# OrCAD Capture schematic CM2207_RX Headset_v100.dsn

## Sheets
1 02. Main: size A4; title: CM2207_RX Headset_Reference_Schematic; rev: 1.00; company: C-MEDIA ELECTRONICS Inc.; note: Main; note: 6F., 100, Sec. 4, Civil Boulevard, Taipei, Taiwan, R.O.C.
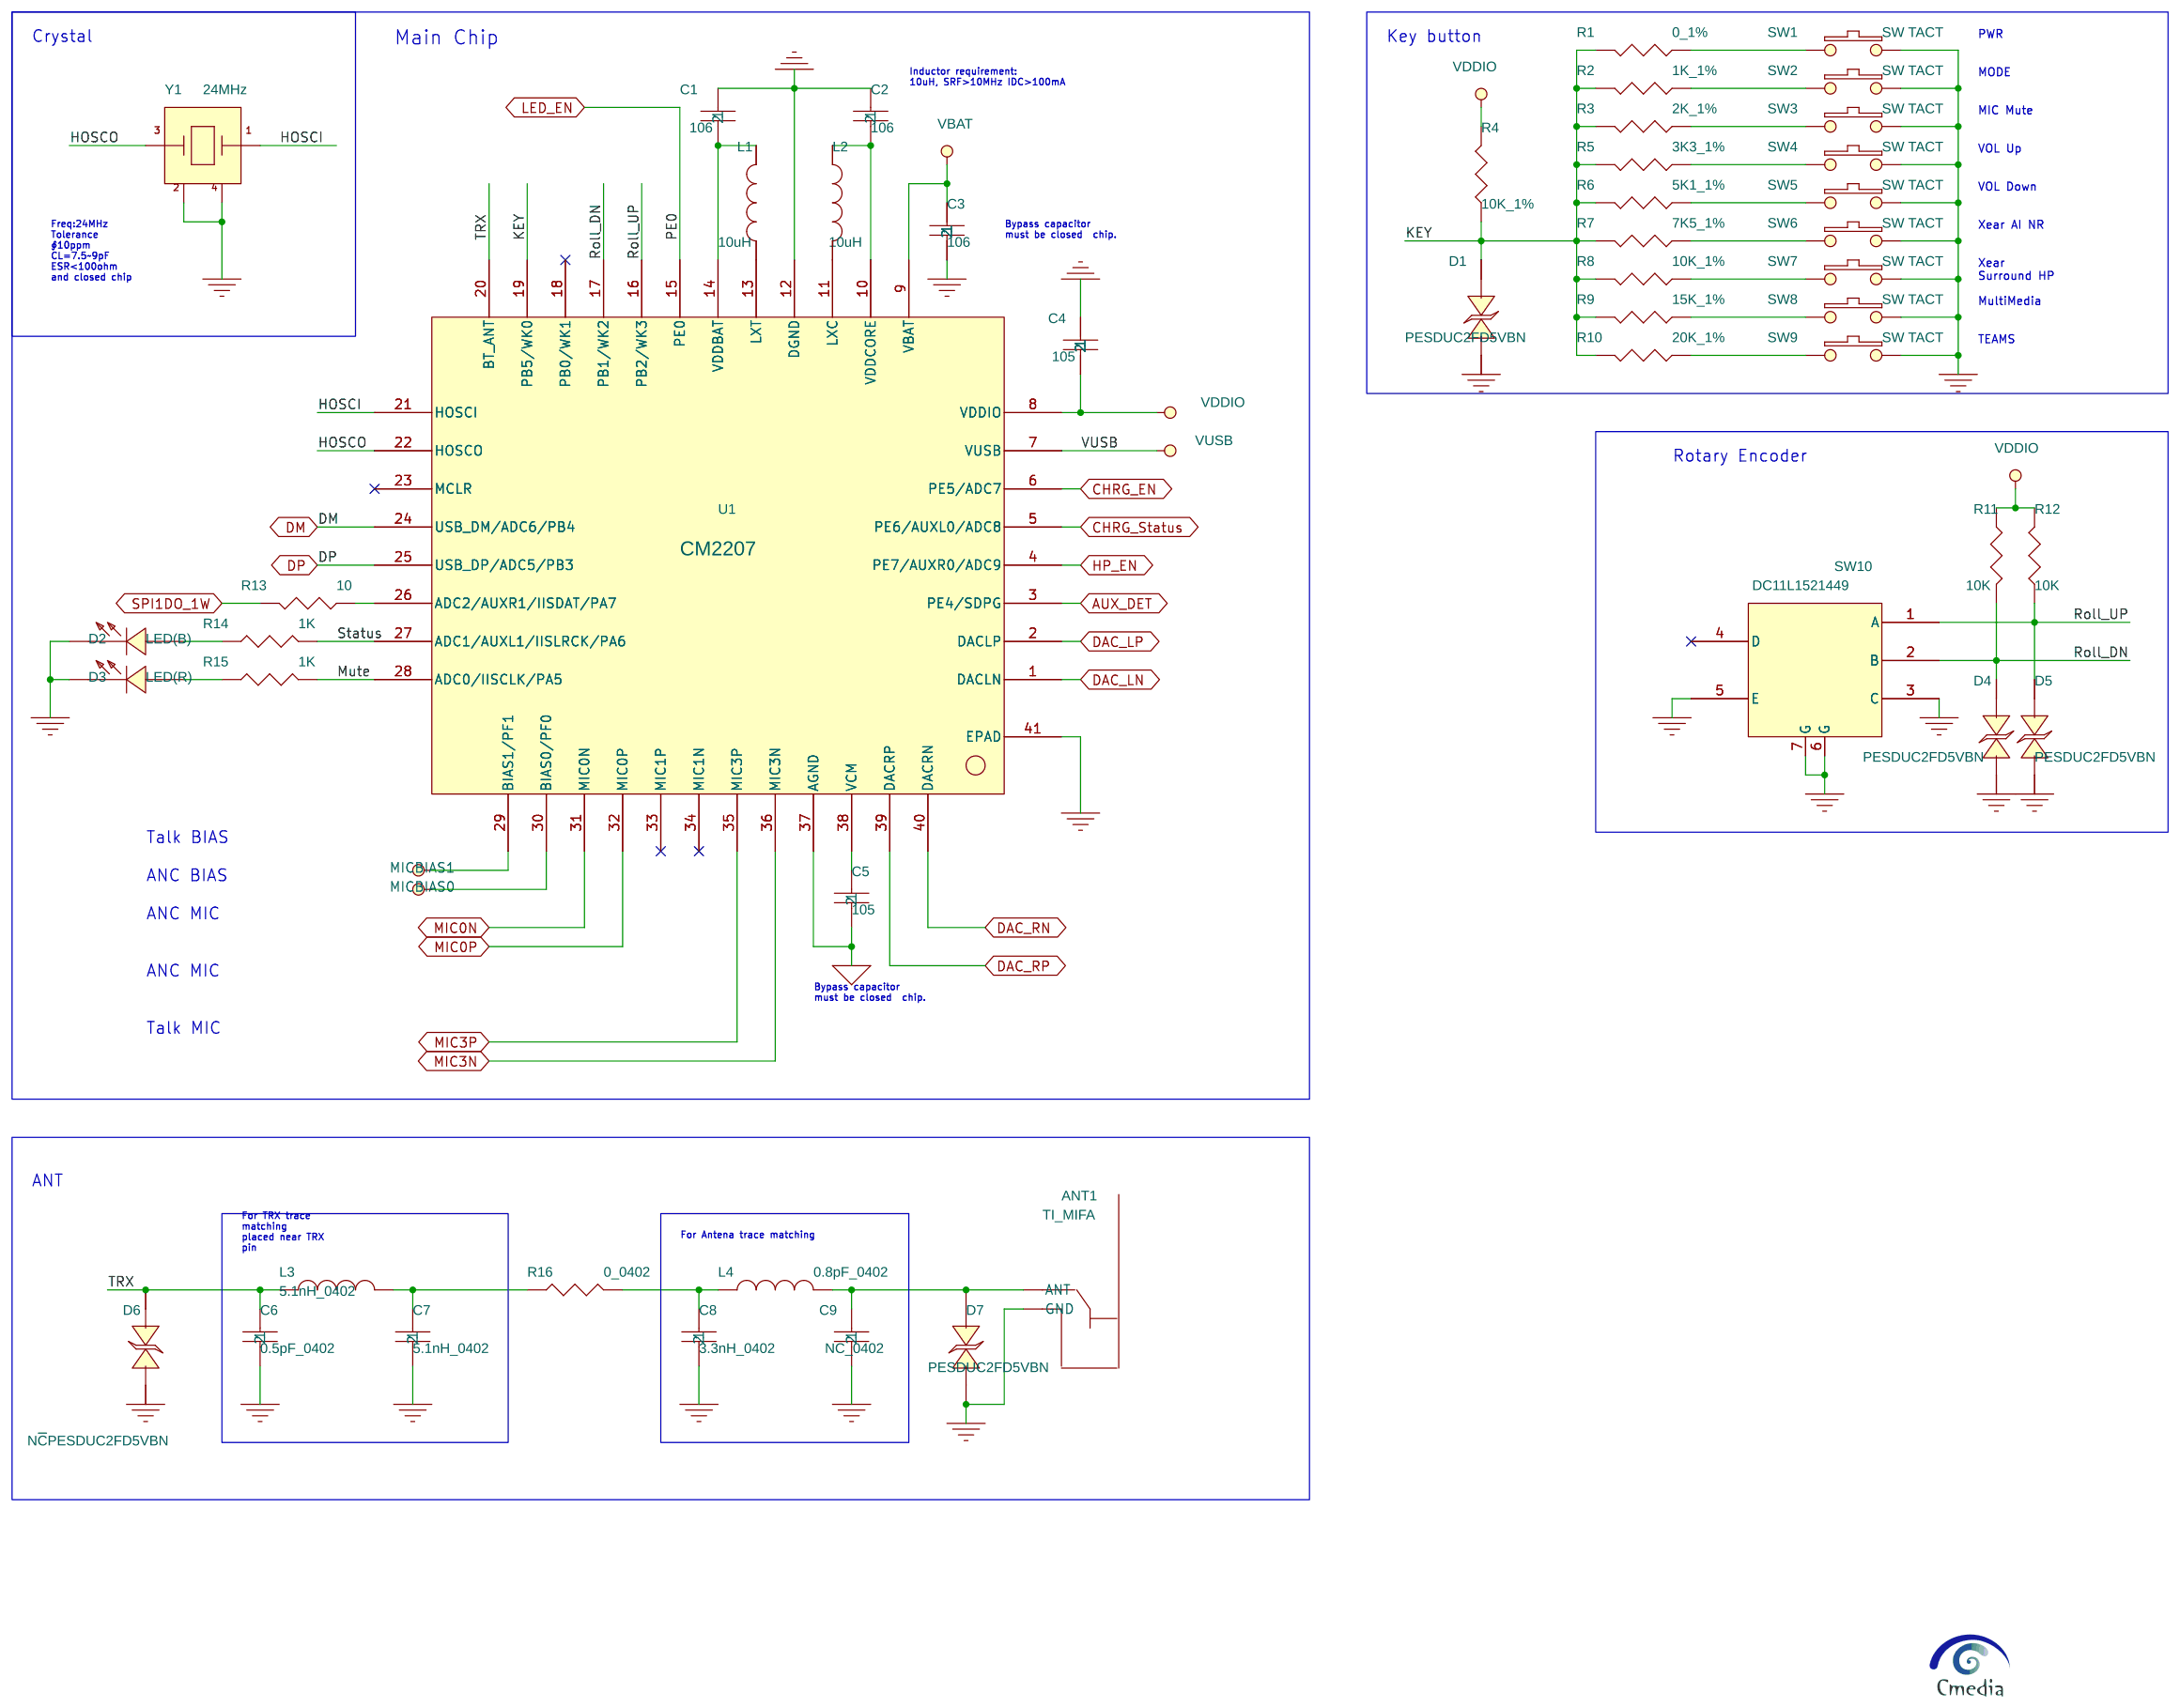
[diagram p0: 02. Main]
2 04. Headphone & Mic In & Aux In: size A4; note: Headphone & Mic In & Aux In
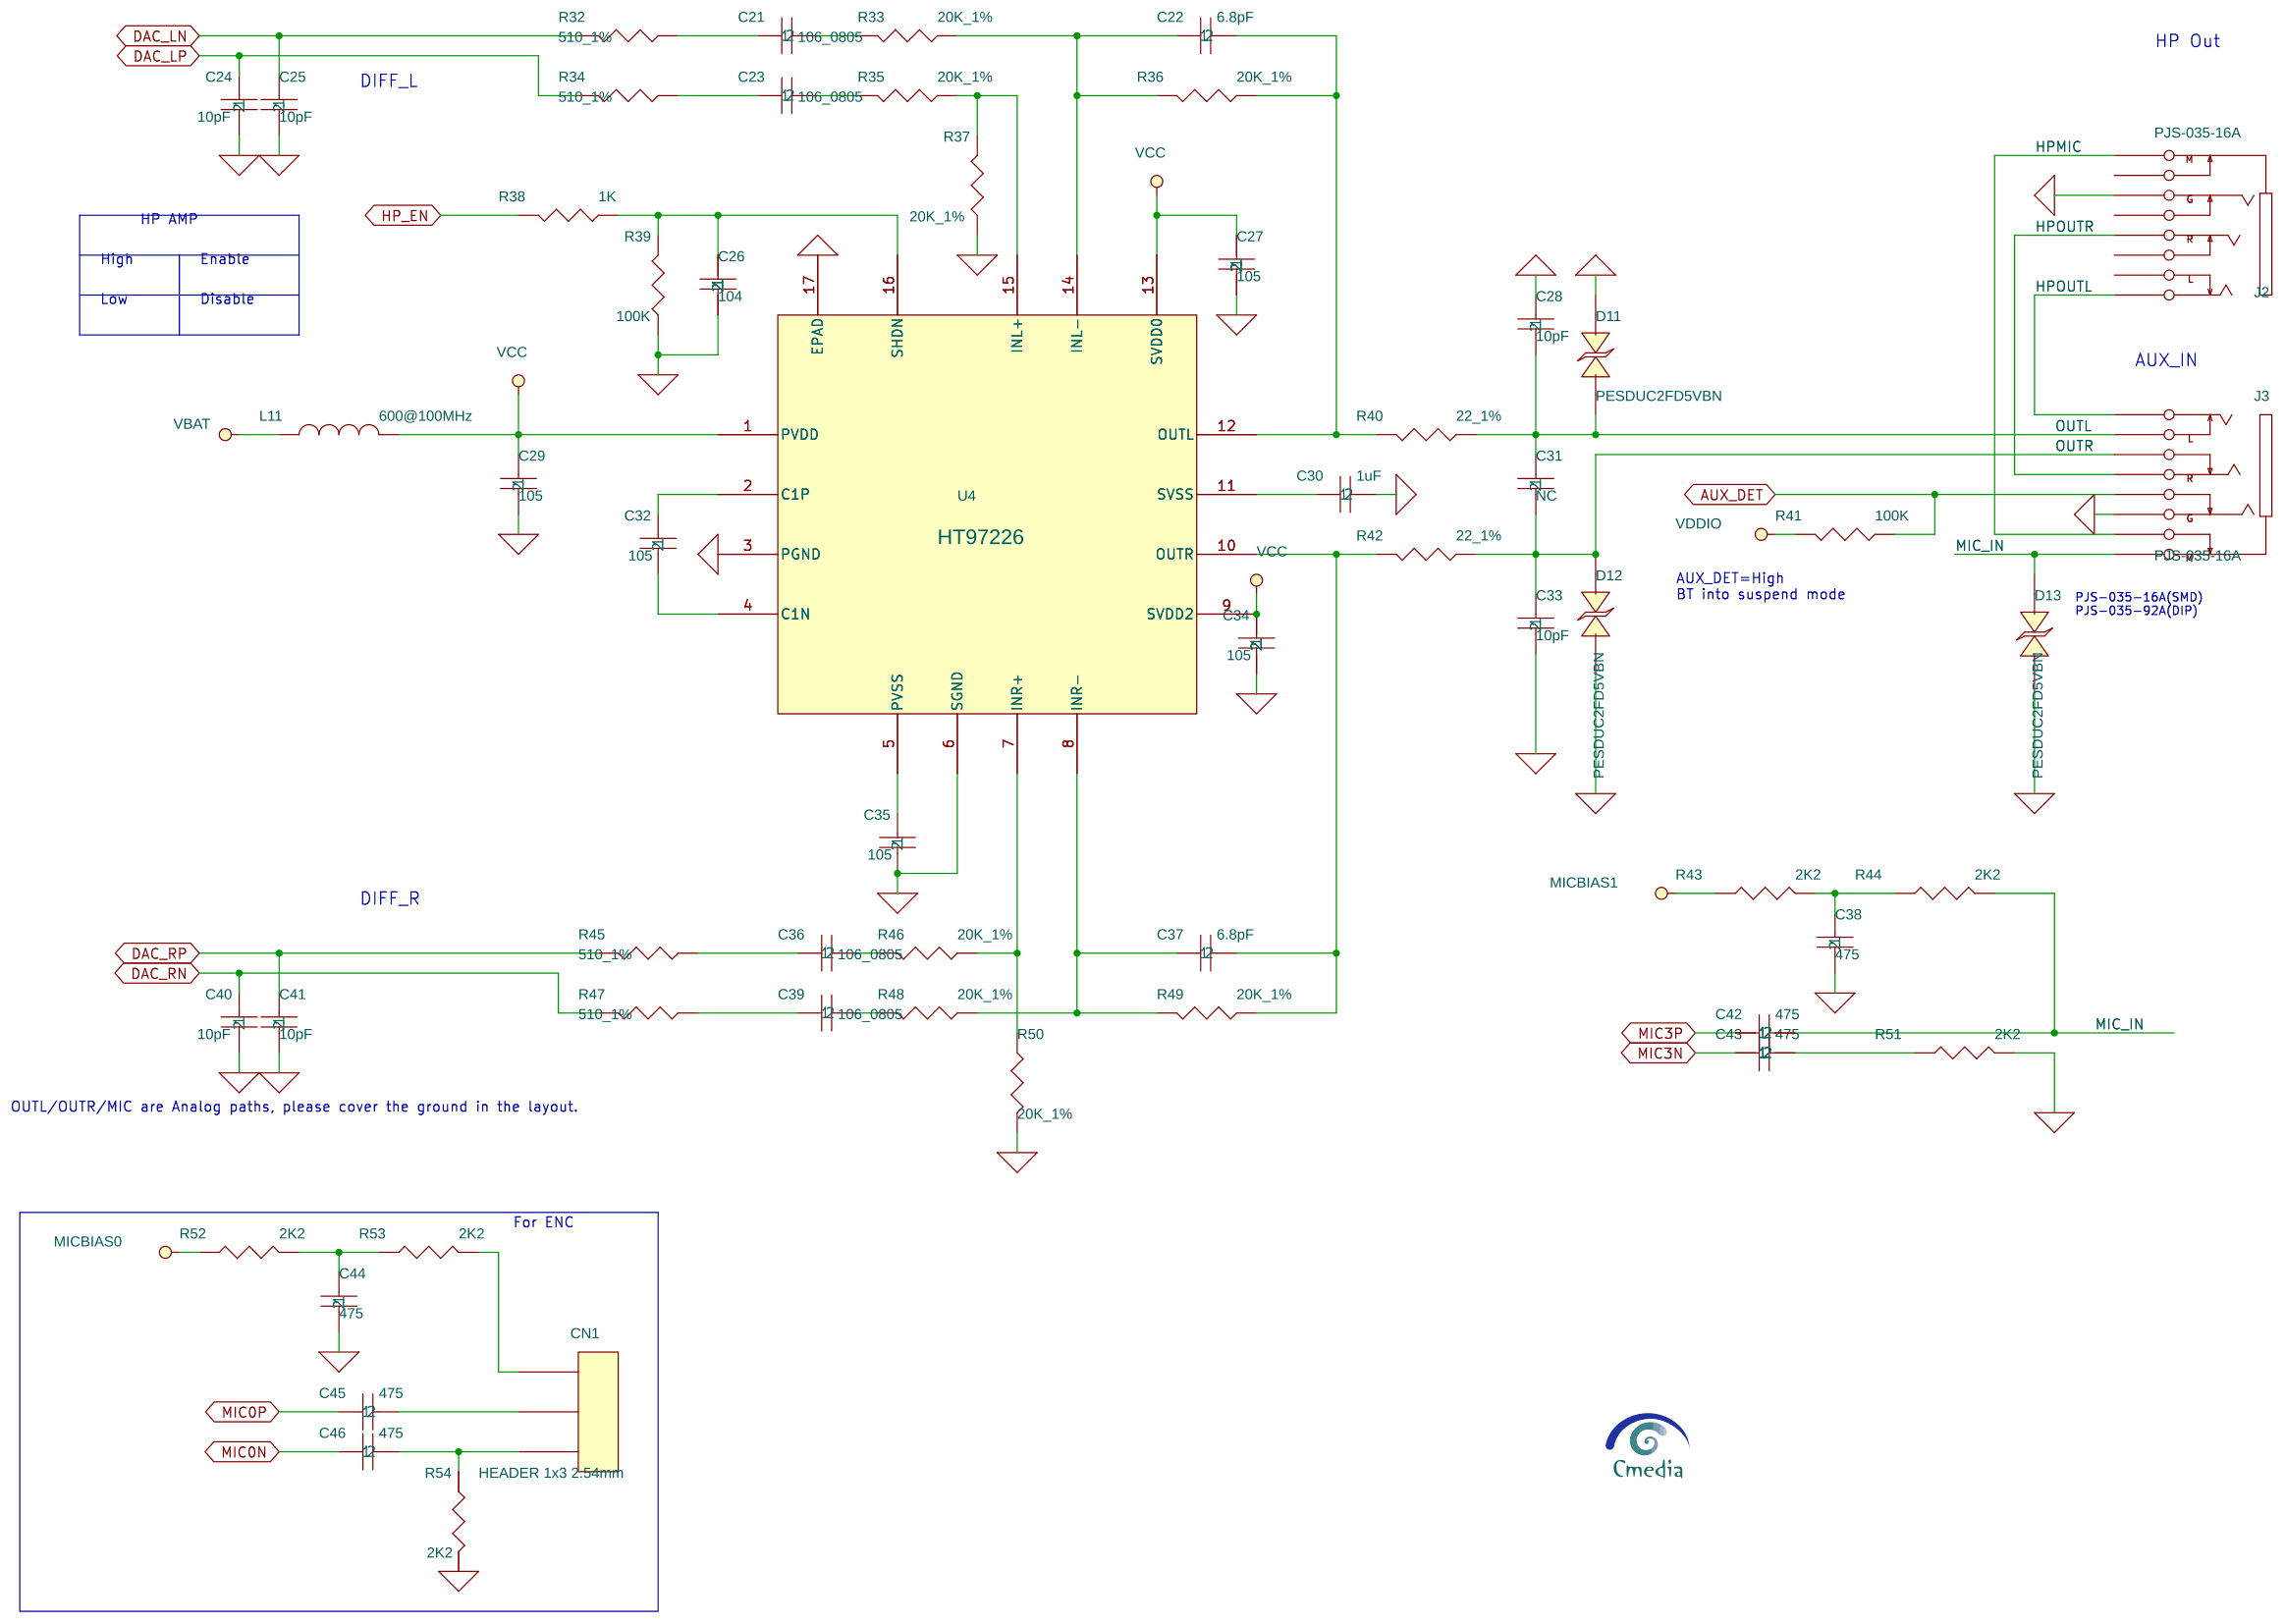
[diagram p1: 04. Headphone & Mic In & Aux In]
3 03. Power/LED: size A4; note: Power
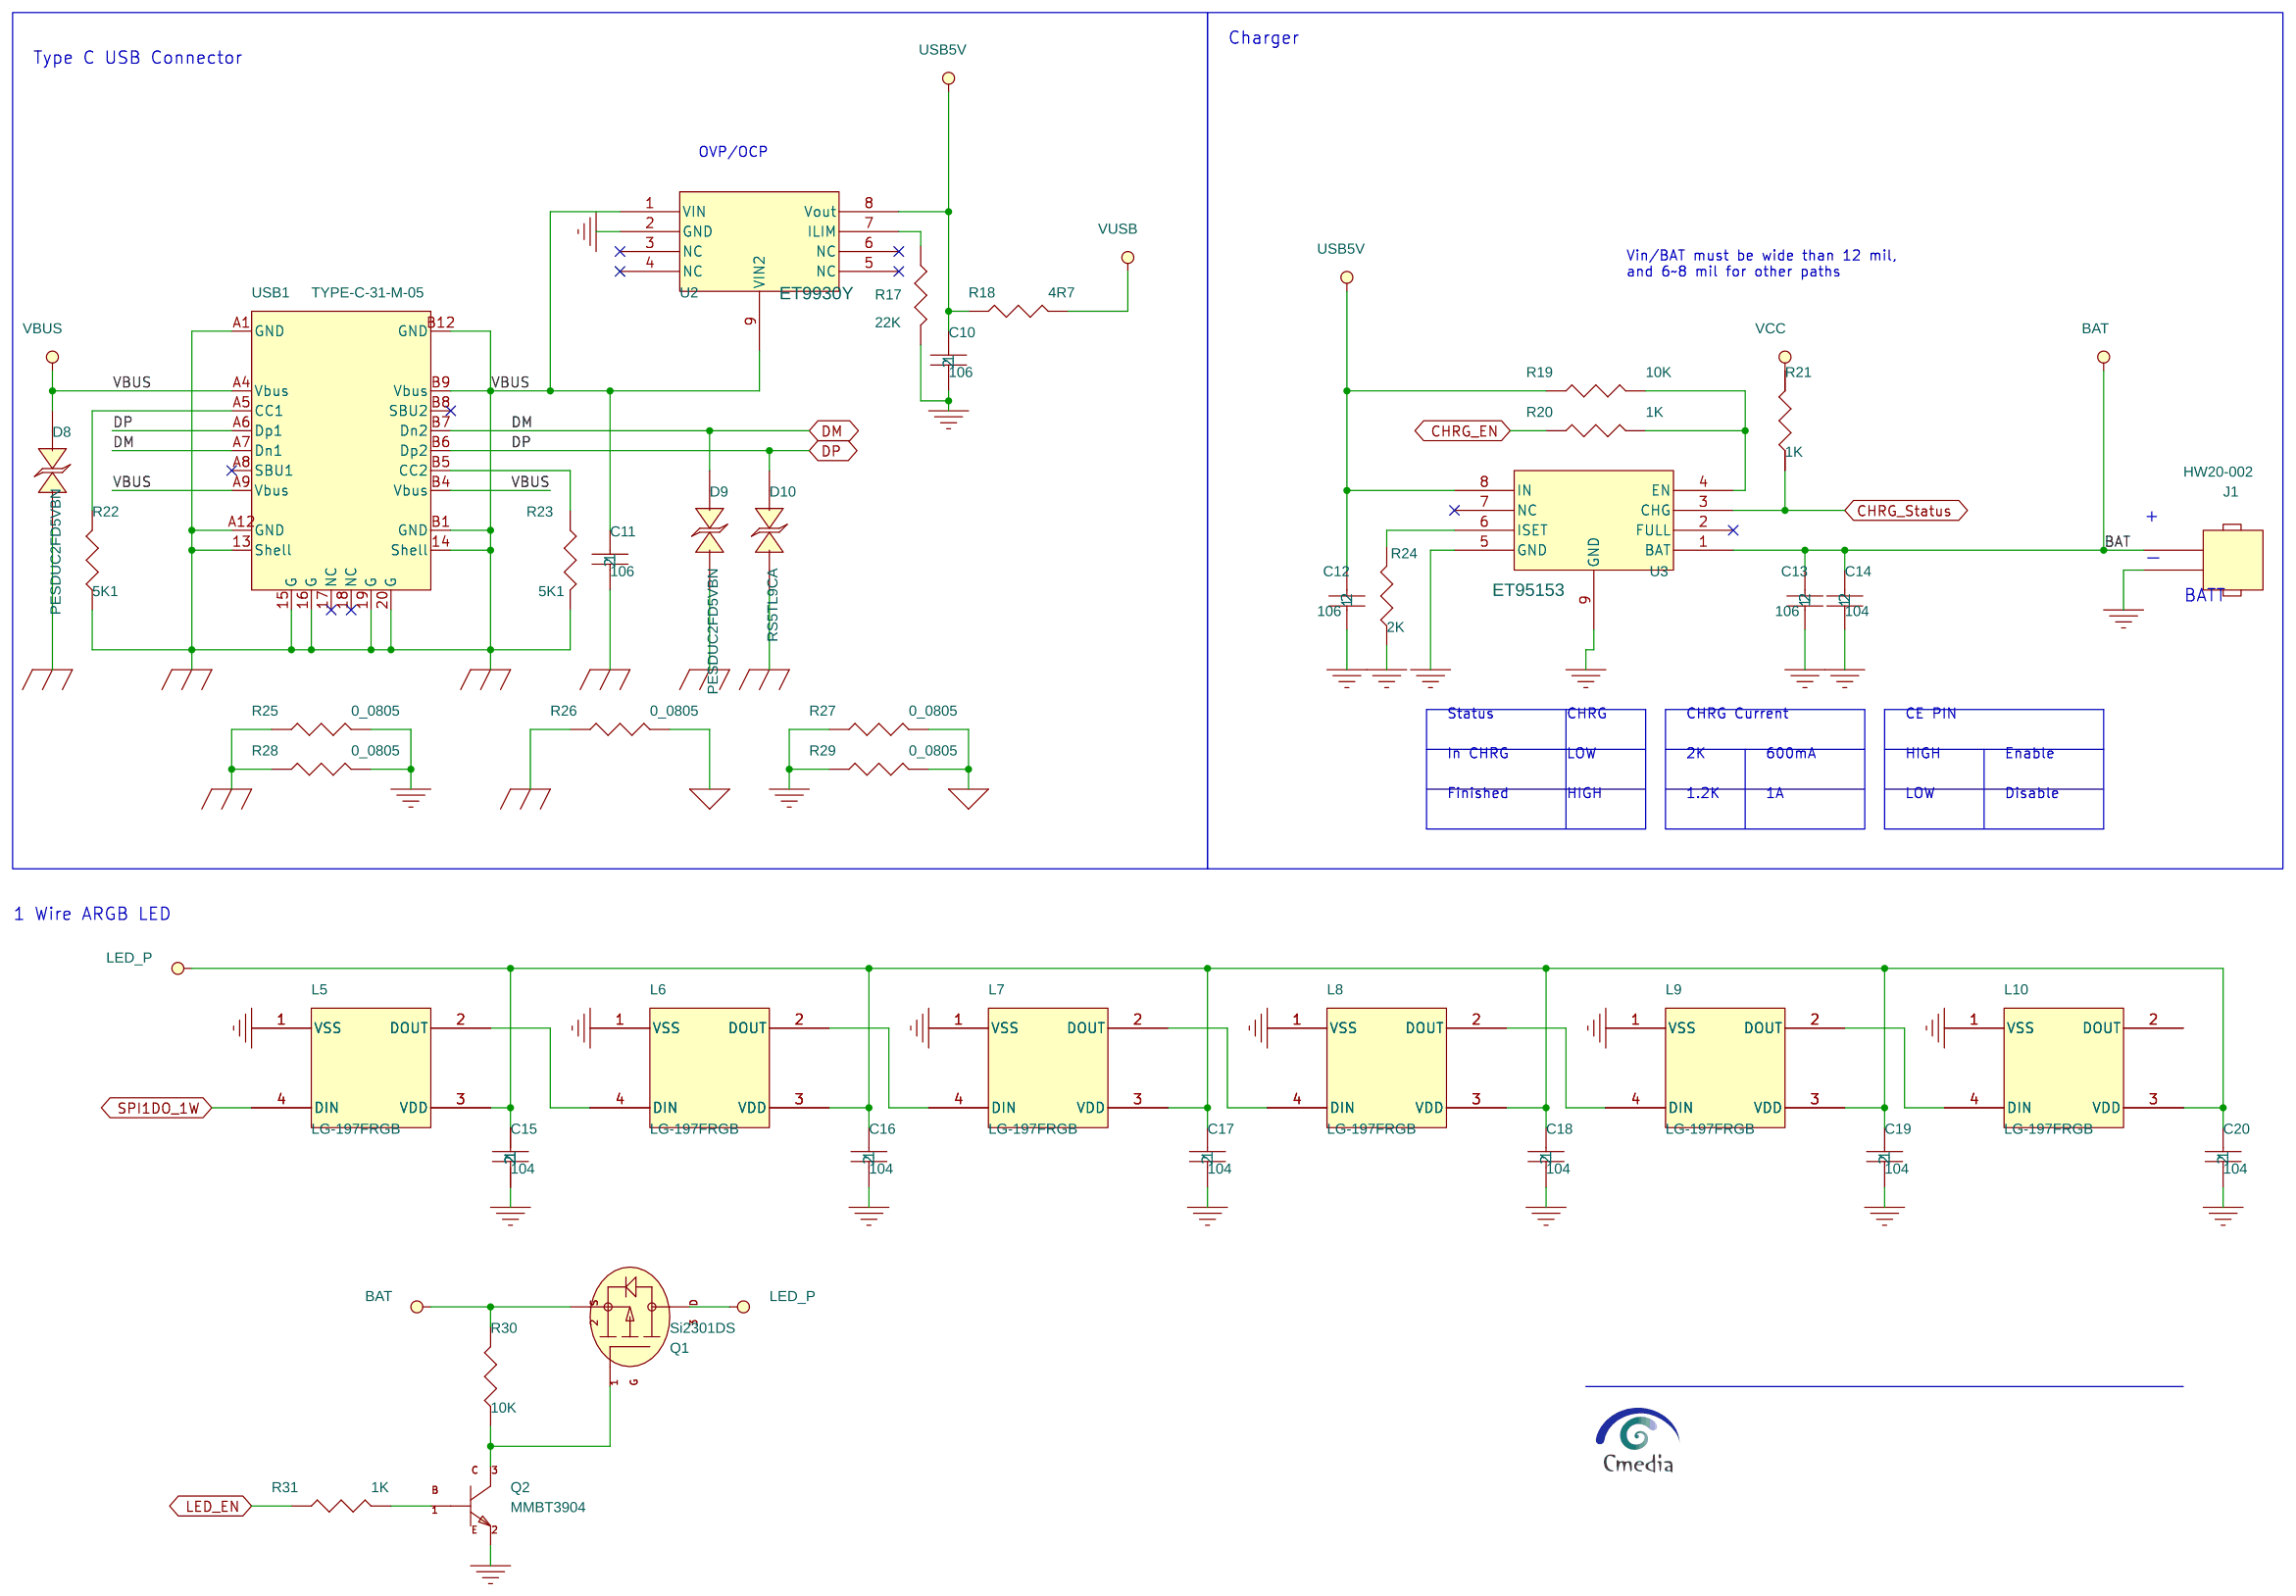
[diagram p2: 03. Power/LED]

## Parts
sheet 02. Main
ANT1  TI_MIFA  [TI_MIFA]
C1  106  [C0603]
C2  106  [C0603]
C3  106  [C0603]
C4  105  [C0603]
C5  105  [C0603]
C6  0.5pF_0402  [C0402]
C7  5.1nH_0402  [C0402]
C8  3.3nH_0402  [C0402]
C9  NC_0402  [C0402]
D1  PESDUC2FD5VBN  [D0402]
D2  LED(B)  [D0603]
D3  LED(R)  [D0603]
D4  PESDUC2FD5VBN  [D0402]
D5  PESDUC2FD5VBN  [D0402]
D6  NC\PESDUC2FD5VBN  [D0402]
D7  PESDUC2FD5VBN  [D0402]
L1  10uH  [L0603]
L2  10uH  [L0603]
L3  5.1nH_0402  [L0402]
L4  0.8pF_0402  [L0402]
R1  0_1%  [R0603]
R2  1K_1%  [R0603]
R3  2K_1%  [R0603]
R4  10K_1%  [R0603]
R5  3K3_1%  [R0603]
R6  5K1_1%  [R0603]
R7  7K5_1%  [R0603]
R8  10K_1%  [R0603]
R9  15K_1%  [R0603]
R10  20K_1%  [R0603]
R11  10K  [R0603]
R12  10K  [R0603]
R13  10  [R0603]
R14  1K  [R0603]
R15  1K  [R0603]
R16  0_0402  [R0402]
SW1  SW TACT  [STSW-39X29]
SW2  SW TACT  [STSW-39X29]
SW3  SW TACT  [STSW-39X29]
SW4  SW TACT  [STSW-39X29]
SW5  SW TACT  [STSW-39X29]
SW6  SW TACT  [STSW-39X29]
SW7  SW TACT  [STSW-39X29]
SW8  SW TACT  [STSW-39X29]
SW9  SW TACT  [STSW-39X29]
SW10  DC11L1521449  [EC11E115244G1]
U1  CM2207  [QFN-40_6X4]
Y1  24MHz  [SOSC-3.2X2]
sheet 03. Power/LED
C10  106  [C0603]
C11  106  [C0603]
C12  106  [C0603]
C13  106  [C0603]
C14  104  [C0603]
C15  104  [C0603]
C16  104  [C0603]
C17  104  [C0603]
C18  104  [C0603]
C19  104  [C0603]
C20  104  [C0603]
D8  PESDUC2FD5VBN  [D0402]
D9  PESDUC2FD5VBN  [D0402]
D10  RS5TL9CA  [D0402]
J1  HW20-002  [J1C2L-PH-90]
L5  LG-197FRGB  [LG-197FRGB]
L6  LG-197FRGB  [LG-197FRGB]
L7  LG-197FRGB  [LG-197FRGB]
L8  LG-197FRGB  [LG-197FRGB]
L9  LG-197FRGB  [LG-197FRGB]
L10  LG-197FRGB  [LG-197FRGB]
Q1  Si2301DS  [SOT-23]
Q2  MMBT3904  [SOT-23]
R17  22K  [R0603]
R18  4R7  [R0603]
R19  10K  [R0603]
R20  1K  [R0603]
R21  1K  [R0603]
R22  5K1  [R0603]
R23  5K1  [R0603]
R24  2K  [R0603]
R25  0_0805  [R0805]
R26  0_0805  [R0805]
R27  0_0805  [R0805]
R28  0_0805  [R0805]
R29  0_0805  [R0805]
R30  10K  [R0603]
R31  1K  [R0603]
U2  ET9930Y  [DFN8(2*2)]
U3  ET95153  [SOP8-PP]
USB1  TYPE-C-31-M-05  [TUSB31CF-073-L-SMD]
sheet 04. Headphone & Mic In & Aux In
C21  106_0805  [C0805]
C22  6.8pF  [C0603]
C23  106_0805  [C0805]
C24  10pF  [C0603]
C25  10pF  [C0603]
C26  104  [C0603]
C27  105  [C0603]
C28  10pF  [C0603]
C29  105  [C0603]
C30  1uF  [C0603]
C31  NC  [C0603]
C32  105  [C0603]
C33  10pF  [C0603]
C34  105  [C0603]
C35  105  [C0603]
C36  106_0805  [C0805]
C37  6.8pF  [C0603]
C38  475  [C0603]
C39  106_0805  [C0805]
C40  10pF  [C0603]
C41  10pF  [C0603]
C42  475  [C0603]
C43  475  [C0603]
C44  475  [C0603]
C45  475  [C0603]
C46  475  [C0603]
CN1  HEADER 1x3 2.54mm  [J1A3]
D11  PESDUC2FD5VBN  [D0402]
D12  PESDUC2FD5VBN  [D0402]
D13  PESDUC2FD5VBN  [D0402]
J2  PJS-035-16A  [PJS-035-16A]
J3  PJS-035-16A  [PJS-035-16A]
L11  600@100MHz  [L0603]
R32  510_1%  [R0603]
R33  20K_1%  [R0603]
R34  510_1%  [R0603]
R35  20K_1%  [R0603]
R36  20K_1%  [R0603]
R37  20K_1%  [R0603]
R38  1K  [R0603]
R39  100K  [R0603]
R40  22_1%  [R0603]
R41  100K  [R0603]
R42  22_1%  [R0603]
R43  2K2  [R0603]
R44  2K2  [R0603]
R45  510_1%  [R0603]
R46  20K_1%  [R0603]
R47  510_1%  [R0603]
R48  20K_1%  [R0603]
R49  20K_1%  [R0603]
R50  20K_1%  [R0603]
R51  2K2  [R0603]
R52  2K2  [R0603]
R53  2K2  [R0603]
R54  2K2  [R0603]
U4  HT97226  [TQFN-3X3-16L]

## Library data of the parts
ANT1 = ANTENNA_1
C1 C17 C42 = CAP_NP_5
C2 C10 C38 = CAP_NP_1
C3 C16 C25 = CAP_NP_6
C4 C20 C43 = CAP_NP
C5 C14 C37 = CAP_NP_2
C6 C15 C45 = CAP_NP_8
C7 C12 C27 = CAP_NP_4
C8 C19 C46 = CAP_NP_7
C9 C18 C40 = CAP_NP_3
D1 D4-D13 = DIODE_TVS_BI-DIR
D2 D3 = LED
L1-L4 L11 = INDUCTOR
R1-R54 = R
SW1-SW9 = SW_TACT-SPST_SM
SW10 = X72011_7
U1 = CMI120_49
Y1 = CRYSTAL_SM_0
C11 C31 = CAP_NP_10
C13 C39 = CAP_NP_9
J1 = HEADER_2
L5-L10 = ZTA_3
Q1 = PWRMOSFET_EP_GSD_5
Q2 = 2N3904_2
U2 = CMI120_48_v2
U3 = CMI120_50
USB1 = HEADER_4_4: 1ST PART FIELD: USB Micro B-Type SMD
C21 = CAP_NP_13
C22 = CAP_NP_19
C23 = CAP_NP_20
C24 = CAP_NP_24
C26 = CAP_NP_17
C28 = CAP_NP_16
C29 = CAP_NP_15
C30 = CAP_NP_23
C32 = CAP_NP_14
C33 = CAP_NP_11
C34 = CAP_NP_22
C35 = CAP_NP_12
C36 = CAP_NP_25
C41 = CAP_NP_18
C44 = CAP_NP_21
CN1 = HEADER_5_13
J2 J3 = PHONEJACK_STEREO_SW_7: Value2: iPhone Jack
U4 = CMI120_46_v2

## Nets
AGND: C5.2 C24.2 C25.2 C26.2 C27.2 C28.1 C29.2 C30.2 C33.2 C34.2 C35.2 C38.2 C40.2 C41.2 C44.2 D11.2 D12.1 D13.1 J2.2 J3.2 R26.1 R27.1 R29.1 R37.1 R39.1 R50.1 R51.1 R54.2 U1.37(AGND) U4.3(PGND) U4.6(SGND) U4.17(EPAD)
DGND: ANT1.2(GND) C1.1 C2.1 C3.2 C4.1 C6.2 C7.2 C8.2 C9.2 C10.2 C12.1 C13.1 C14.1 C15.2 C16.2 C17.2 C18.2 C19.2 C20.2 D1.1 D2.2(CATHODE) D3.2(CATHODE) D4.1 D5.1 D6.1 D7.1 J1.2 L5.1(VSS) L6.1(VSS) L7.1(VSS) L8.1(VSS) L9.1(VSS) L10.1(VSS) Q2.2(EMITTER) R17.1 R24.1 R25.1 R27.2 R28.1 R29.2 SW1.2 SW2.2 SW3.2 SW4.2 SW5.2 SW6.2 SW7.2 SW8.2 SW9.2 SW10.3(C) SW10.5(E) SW10.6(G) SW10.7(G) U1.12(DGND) U1.41(EPAD) U2.2(GND) U3.5(GND) U3.9(GND) Y1.2 Y1.4
GND_EARTH: C11.2 D8.1 D9.1 D10.1 R22.1 R23.1 R25.2 R26.2 R28.2 USB1.13(Shell) USB1.14(Shell) USB1.15(G) USB1.16(G) USB1.19(G) USB1.20(G) USB1.A1(GND) USB1.A12(GND) USB1.B1(GND) USB1.B12(GND)
VBAT: C3.1 C13.2 C14.2 J1.1 L11.1 Q1.2(SOURCE) R30.1 U1.9(VBAT) U3.1(BAT)
VBUS: C11.1 D8.2 U2.1(VIN) U2.9(VIN2) USB1.A4(Vbus) USB1.A9(Vbus) USB1.B4(Vbus) USB1.B9(Vbus)
VCC: C27.1 C29.1 C34.1 L11.2 U4.1(PVDD) U4.9(SVDD2) U4.13(SVDD0)
VDDIO: C4.2 R4.2 R11.2 R12.2 R21.1 R41.1 U1.8(VDDIO)
AUX_DET: J3.6 R41.2 U1.3(PE4/SDPG)
CHRG_EN: R20.2 U1.6(PE5/ADC7)
CHRG_Status: R21.2 U1.5(PE6/AUXL0/ADC8) U3.3(CHG)
DAC_LN: C25.1 R32.1 U1.1(DACLN)
DAC_LP: C24.1 R34.1 U1.2(DACLP)
DAC_RN: C40.1 R47.1 U1.40(DACRN)
DAC_RP: C41.1 R45.1 U1.39(DACRP)
DM: D9.2 U1.24(USB_DM/ADC6/PB4) USB1.A7(Dn1) USB1.B7(Dn2)
DP: D10.2 U1.25(USB_DP/ADC5/PB3) USB1.A6(Dp1) USB1.B6(Dp2)
HOSCI: U1.21(HOSCI) Y1.1
HOSCO: U1.22(HOSCO) Y1.3
HP_EN: R38.1 U1.4(PE7/AUXR0/ADC9)
HPMIC: J2.1 J3.5
HPOUTL: J2.8 J3.8
HPOUTR: J2.3 J3.3
KEY: D1.2 R1.2 R2.2 R3.2 R4.1 R5.2 R6.2 R7.2 R8.2 R9.2 R10.2 U1.19(PB5/WK0)
LED_EN: R31.2 U1.15(PE0)
LED_P: C15.1 C16.1 C17.1 C18.1 C19.1 C20.1 L5.3(VDD) L6.3(VDD) L7.3(VDD) L8.3(VDD) L9.3(VDD) L10.3(VDD) Q1.3(DRAIN)
MIC0N: C46.1 U1.31(MIC0N)
MIC0P: C45.1 U1.32(MIC0P)
MIC3N: C43.1 U1.36(MIC3N)
MIC3P: C42.1 U1.35(MIC3P)
MIC_IN: C42.2 D13.2 J3.1 R44.1
MICBIAS0: R52.2 U1.30(BIAS0/PF0)
MICBIAS1: R43.2 U1.29(BIAS1/PF1)
Mute: R15.2 U1.28(ADC0/IISCLK/PA5)
OUTL: C28.2 C31.1 D11.1 J3.4 R40.2
OUTR: C31.2 C33.1 D12.2 J3.7 R42.2
Roll_DN: D4.2 R11.1 SW10.2(B) U1.17(PB1/WK2)
Roll_UP: D5.2 R12.1 SW10.1(A) U1.16(PB2/WK3)
SPI1DO_1W: L5.4(DIN) R13.2
Status: R14.2 U1.27(ADC1/AUXL1/IISLRCK/PA6)
TRX: C6.1 D6.2 L3.1 U1.20(BT_ANT)
USB5V: C10.1 C12.2 R18.2 R19.2 U2.8(Vout) U3.8(IN)
VUSB: R18.1 U1.7(VUSB)
N27635076: C32.1 U4.2(C1P)
N27635081: C32.2 U4.4(C1N)
N27636514: C36.2 R46.1
N27636561: C39.2 R48.1
N27636802: R46.2 R50.2 U4.7(INR+)
N27636807: C37.1 R48.2 R49.1 U4.8(INR-)
N27637340: C37.2 R42.1 R49.2 U4.10(OUTR)
N27637610: C30.1 U4.11(SVSS)
N27638173: C39.1 R47.2
N27638886: C26.1 R38.2 R39.2 U4.16(SHDN)
N27639116: C21.2 R33.1
N27639137: C23.2 R35.1
N27639166: R35.2 R37.2 U4.15(INL+)
N27639169: C22.1 R33.2 R36.1 U4.14(INL-)
N27639436: C22.2 R36.2 R40.1 U4.12(OUTL)
N27646527: C38.1 R43.1 R44.2
N27646596: C43.2 R51.2
N27719318: C36.1 R45.2
N27719805: C23.1 R34.2
N27719894: C21.1 R32.2
N27795412: C35.1 U4.5(PVSS)
N27890741: L5.2(DOUT) L6.4(DIN)
N27891740: L6.2(DOUT) L7.4(DIN)
N27891907: L7.2(DOUT) L8.4(DIN)
N27892813: L8.2(DOUT) L9.4(DIN)
N27892991: L9.2(DOUT) L10.4(DIN)
N27908673: R13.1 U1.26(ADC2/AUXR1/IISDAT/PA7)
N27917773: Q1.1(GATE) Q2.3(COLLECTOR) R30.2
N27918264: Q2.1(BASE) R31.1
N27926824: C1.2 L1.2 U1.14(VDDBAT)
N27926828: C2.2 L2.2 U1.10(VDDCORE)
N27927035: C5.1 U1.38(VCM)
N27939666: R19.1 R20.1 U3.4(EN)
N27939678: R22.2 USB1.A5(CC1)
N27939741: R23.2 USB1.B5(CC2)
N27941972: R1.1 SW1.1
N27942002: R2.1 SW2.1
N27942030: R3.1 SW3.1
N27942064: R5.1 SW4.1
N27942090: R6.1 SW5.1
N27942125: R7.1 SW6.1
N27942159: R8.1 SW7.1
N27942185: R9.1 SW8.1
N27942209: R10.1 SW9.1
N27943747: D2.1(ANODE) R14.1
N27943769: D3.1(ANODE) R15.1
N27946639: C44.1 R52.1 R53.2
N27946645: CN1.1 R53.1
N27946687: C45.2 CN1.2
N27946704: C46.2 CN1.3 R54.1
N27948516: C7.1 L3.2 R16.2
N27948522: C8.1 L4.1 R16.1
N27948528: ANT1.1(ANT) C9.1 D7.2 L4.2
N27950934: R17.2 U2.7(ILIM)
N27953267: L1.1 U1.13(LXT)
N27953268: L2.1 U1.11(LXC)
N27954862: R24.2 U3.6(ISET)

Not connected (* = marked no-connect by the designer): J2 4 5 6 7; L10 2(DOUT); SW10 4(D)*; U1 18(PB0/WK1)* 23(MCLR)* 33(MIC1P)* 34(MIC1N)*; U2 3(NC)* 4(NC)* 5(NC)* 6(NC)*; U3 2(FULL)* 7(NC)*; USB1 17(NC)* 18(NC)* A8(SBU1)* B8(SBU2)*

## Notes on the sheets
sheet 1
- Crystal
- Main Chip
- Key button
- PWR
- Inductor requirement:
  10uH, SRF>10MHz IDC>100mA
- MODE
- MIC Mute
- VOL Up
- VOL Down
- Freq:24MHz
  Tolerance
  ∮10ppm
  CL=7.5~9pF
  ESR<100ohm
  and closed chip
- Bypass capacitor
  must be closed  chip.
- Xear AI NR
- Xear
  Surround HP
- MultiMedia
- TEAMS
- Rotary Encoder
- Talk BIAS
- ANC BIAS
- ANC MIC
- ANC MIC
- Bypass capacitor
  must be closed  chip.
- Talk MIC
- ANT
- For TRX trace
  matching
  placed near TRX
  pin
- For Antena trace matching
sheet 2
- HP Out
- DIFF_L
- HP AMP
- High
- Enable
- Low
- Disable
- AUX_IN
- AUX_DET=High
  BT into suspend mode
- PJS-035-16A(SMD)
  PJS-035-92A(DIP)
- DIFF_R
- OUTL/OUTR/MIC are Analog paths, please cover the ground in the layout.
- For ENC
sheet 3
- Charger
- Type C USB Connector
- OVP/OCP
- Vin/BAT must be wide than 12 mil,
  and 6~8 mil for other paths
- +
- -
- BATT
- Status
- CHRG
- CHRG Current
- CE PIN
- In CHRG
- LOW
- 2K
- 600mA
- HIGH
- Enable
- Finished
- HIGH
- 1.2K
- 1A
- LOW
- Disable
- 1 Wire ARGB LED
